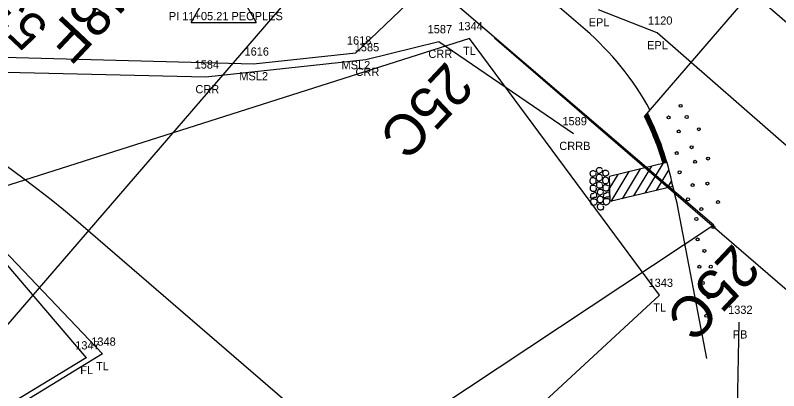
# Model space of a CAD drawing. Extents: x 1812113 to 1819860, y 1177395 to 1181185.
# Drawn here: x 1813697.5 to 1813790.4, y 1178629.6 to 1178675.3 of the extents above; entities that cross this region are included whole.
import ezdxf

# ---------------------------------------------------------------- set-up
doc = ezdxf.new("R2010")
doc.units = 0
for name, color, linetype in [('RD_EX_DR_Pipe', 7, 'Continuous'), ('RD_EX_DR_Pipe_txCode', 7, 'Continuous'), ('RD_EX_Fence_Other', 7, 'Continuous'), ('RD_EX_Fence_Other_txCode', 7, 'Continuous'), ('RD_EX_H2O', 7, 'Continuous'), ('RD_EX_H2O_txCode', 7, 'Continuous'), ('RD_EX_Misc', 7, 'Continuous'), ('RD_EX_Misc_txCode', 7, 'Continuous'), ('RD_EX_Road', 7, 'Continuous'), ('RD_EX_Road_txCode', 7, 'Continuous'), ('RD_EX_RW', 7, 'Continuous'), ('RD_EX_VEG', 7, 'Continuous'), ('RD_EX_VEG_txCode', 7, 'Continuous'), ('RD_HC_Data', 7, 'Continuous'), ('RD_HC_txCode', 7, 'Continuous'), ('RD_PD_ALT1_TrvlWay', 7, 'Continuous'), ('RD_PD_ALT3_LnLine', 7, 'Continuous'), ('RD_PD_Bridge', 7, 'Continuous'), ('RD_PD_PatLn1', 7, 'Continuous'), ('RD_PD_RW', 7, 'Continuous'), ('RD_SMD_Locator', 7, 'Continuous')]:
    doc.layers.add(name, color=color, linetype=linetype)

msp = doc.modelspace()

# ---------------------------------------------------------------- linework, layer by layer
at = {"layer": 'RD_EX_DR_Pipe'}
msp.add_line((1813784.669, 1178591.737), (1813785.572, 1178637.964), dxfattribs=at)
at = {"layer": 'RD_EX_Fence_Other'}
msp.add_lwpolyline([(1813689.162, 1178653.472), (1813706.151, 1178633.635), (1813541.418, 1178533.615)], dxfattribs=at)
at = {"layer": 'RD_EX_H2O'}
msp.add_lwpolyline([(1813494.934, 1178677.139), (1813538.082, 1178685.025), (1813548.669, 1178684.396), (1813554.063, 1178674.831), (1813572.775, 1178667.802), (1813599.795, 1178663.176), (1813623.262, 1178662.124), (1813655.354, 1178662.604), (1813687.646, 1178668.532), (1813720.678, 1178667.781), (1813740.155, 1178669.888), (1813749.02, 1178672.079), (1813765.419, 1178660.888)], dxfattribs=at)
at = {"layer": 'RD_EX_Misc'}
msp.add_lwpolyline([(1813591.145, 1178668.772), (1813628.984, 1178667.844), (1813655.761, 1178668.83), (1813686.954, 1178670.41), (1813726.51, 1178669.36), (1813738.941, 1178670.711), (1813788.676, 1178718.193), (1813806.253, 1178725.658), (1813819.179, 1178726.191), (1813847.084, 1178721.307), (1813860.38, 1178717.648), (1813871.967, 1178724.247), (1813883.921, 1178723.481), (1813902.674, 1178722.415)], dxfattribs=at)
at = {"layer": 'RD_EX_Road'}
for p, q in [((1813775.579, 1178673.127), (1813768.463, 1178675.914)), ((1813800.257, 1178651.571), (1813775.579, 1178673.127))]:
    msp.add_line(p, q, dxfattribs=at)
at = {"layer": 'RD_EX_RW'}
for q in [(1813739.051, 1178686.932), (1813724.979, 1178611.658)]:
    msp.add_line((1813782.499, 1178649.754), q, dxfattribs=at)
at = {"layer": 'RD_EX_VEG'}
msp.add_lwpolyline([(1813569.577, 1178500.764), (1813635.352, 1178535.148), (1813737.799, 1178606.062), (1813775.895, 1178641.246), (1813752.752, 1178672.453), (1813690.463, 1178652.624), (1813708.106, 1178634.089), (1813540.707, 1178531.719)], dxfattribs=at)
at = {"layer": 'RD_HC_Data'}
for p, q in [((1813755.38, 1178705.862), (1813645.021, 1178577.927)), ((1813718.894, 1178674.376), (1813722.866, 1178681.256)), ((1813722.866, 1178681.256), (1813726.835, 1178674.376)), ((1813718.894, 1178674.376), (1813726.835, 1178674.376))]:
    msp.add_line(p, q, dxfattribs=at)
at = {"layer": 'RD_PD_ALT1_TrvlWay'}
for p, q in [((1813774.756, 1178663.814), (1813774.054, 1178663.001)), ((1813776.792, 1178657.372), (1813769.781, 1178655.674)), ((1813774.917, 1178656.918), (1813772.707, 1178653.296)), ((1813776.291, 1178657.251), (1813774.082, 1178653.629)), ((1813770.793, 1178655.919), (1813769.824, 1178654.33)), ((1813772.168, 1178656.252), (1813769.958, 1178652.63)), ((1813773.543, 1178656.585), (1813771.333, 1178652.963)), ((1813777.003, 1178656.498), (1813775.456, 1178653.962)), ((1813769.878, 1178652.611), (1813769.781, 1178655.674)), ((1813777.336, 1178655.123), (1813776.831, 1178654.295)), ((1813777.498, 1178654.456), (1813769.878, 1178652.611)), ((1813781.632, 1178633.542), (1813778.204, 1178651.541))]:
    msp.add_line(p, q, dxfattribs=at)
for centre in [(1813778.439, 1178664.256), (1813776.979, 1178662.847), (1813779.188, 1178662.893), (1813780.666, 1178661.416), (1813778.223, 1178661.141), (1813777.979, 1178658.509), (1813779.786, 1178659.219), (1813781.8, 1178657.843), (1813780.211, 1178657.451), (1813778.326, 1178656.173), (1813781.717, 1178654.805), (1813779.908, 1178654.622), (1813779.344, 1178652.885), (1813782.994, 1178652.546), (1813780.968, 1178651.698), (1813780.362, 1178650.492), (1813782.437, 1178649.505), (1813780.513, 1178648.004), (1813781.349, 1178646.621), (1813780.745, 1178644.684), (1813782.119, 1178644.697), (1813781.142, 1178642.714), (1813781.844, 1178640.982), (1813781.566, 1178638.729)]:
    msp.add_circle(centre, 0.182, dxfattribs=at)
for centre, radius, start, end in [((1813744.086, 1178647.916), 33.935, 16.13386, 26.98789), ((1813744.086, 1178647.916), 33.99, 16.12977, 27.02575), ((1813744.086, 1178647.916), 34.045, 11.0753, 27.06348), ((1813744.086, 1178647.916), 33.55, 16.1628, 26.71909), ((1813744.086, 1178647.916), 33.605, 16.15862, 26.7579), ((1813744.086, 1178647.916), 33.66, 16.15446, 26.79657), ((1813744.086, 1178647.916), 33.715, 16.15031, 26.83511), ((1813744.086, 1178647.916), 33.77, 16.14618, 26.87351), ((1813744.086, 1178647.916), 33.825, 16.14206, 26.91177), ((1813744.086, 1178647.916), 33.88, 16.13795, 26.9499), ((1813744.322, 1178644.902), 34.526, 11.08496, 17.1518)]:
    msp.add_arc(centre, radius, start, end, dxfattribs=at)
for points in [[(1813768.14, 1178656.085), (1813768.127, 1178655.891), (1813768.019, 1178655.757), (1813767.866, 1178655.684), (1813767.674, 1178655.647), (1813767.54, 1178655.754), (1813767.478, 1178655.933), (1813767.46, 1178656.113), (1813767.53, 1178656.264), (1813767.664, 1178656.368), (1813767.844, 1178656.38), (1813768.014, 1178656.317), (1813768.136, 1178656.203)], [(1813768.913, 1178655.623), (1813768.919, 1178655.436), (1813768.856, 1178655.26), (1813768.71, 1178655.162), (1813768.531, 1178655.094), (1813768.362, 1178655.145), (1813768.276, 1178655.298), (1813768.208, 1178655.476), (1813768.215, 1178655.657), (1813768.297, 1178655.809), (1813768.43, 1178655.937), (1813768.617, 1178655.937), (1813768.788, 1178655.849), (1813768.904, 1178655.697)], [(1813768.911, 1178656.475), (1813768.898, 1178656.282), (1813768.791, 1178656.148), (1813768.637, 1178656.074), (1813768.445, 1178656.037), (1813768.311, 1178656.145), (1813768.25, 1178656.324), (1813768.232, 1178656.503), (1813768.301, 1178656.655), (1813768.435, 1178656.759), (1813768.615, 1178656.771), (1813768.785, 1178656.708), (1813768.907, 1178656.593)], [(1813769.675, 1178656.133), (1813769.662, 1178655.94), (1813769.555, 1178655.806), (1813769.401, 1178655.732), (1813769.209, 1178655.695), (1813769.075, 1178655.803), (1813769.014, 1178655.982), (1813768.995, 1178656.161), (1813769.065, 1178656.313), (1813769.199, 1178656.417), (1813769.379, 1178656.429), (1813769.549, 1178656.366), (1813769.671, 1178656.251)], [(1813768.142, 1178655.232), (1813768.148, 1178655.046), (1813768.085, 1178654.869), (1813767.939, 1178654.771), (1813767.76, 1178654.704), (1813767.59, 1178654.754), (1813767.505, 1178654.907), (1813767.437, 1178655.085), (1813767.443, 1178655.266), (1813767.526, 1178655.418), (1813767.659, 1178655.547), (1813767.846, 1178655.546), (1813768.016, 1178655.458), (1813768.133, 1178655.307)], [(1813768.9, 1178654.725), (1813768.971, 1178654.496), (1813768.83, 1178654.282), (1813768.643, 1178654.234), (1813768.474, 1178654.249), (1813768.302, 1178654.37), (1813768.254, 1178654.557), (1813768.249, 1178654.725), (1813768.286, 1178654.894), (1813768.429, 1178655.004), (1813768.597, 1178655.009), (1813768.767, 1178654.951), (1813768.917, 1178654.851)], [(1813769.677, 1178655.281), (1813769.683, 1178655.094), (1813769.62, 1178654.918), (1813769.474, 1178654.82), (1813769.295, 1178654.752), (1813769.126, 1178654.803), (1813769.04, 1178654.956), (1813768.972, 1178655.134), (1813768.979, 1178655.315), (1813769.061, 1178655.467), (1813769.194, 1178655.595), (1813769.381, 1178655.595), (1813769.552, 1178655.507), (1813769.668, 1178655.355)], [(1813768.129, 1178654.334), (1813768.2, 1178654.105), (1813768.059, 1178653.891), (1813767.872, 1178653.843), (1813767.703, 1178653.859), (1813767.531, 1178653.979), (1813767.483, 1178654.167), (1813767.478, 1178654.335), (1813767.515, 1178654.504), (1813767.658, 1178654.613), (1813767.826, 1178654.619), (1813767.996, 1178654.561), (1813768.146, 1178654.461)], [(1813769.015, 1178653.824), (1813769.003, 1178653.63), (1813768.895, 1178653.496), (1813768.741, 1178653.423), (1813768.55, 1178653.386), (1813768.415, 1178653.493), (1813768.354, 1178653.672), (1813768.336, 1178653.852), (1813768.406, 1178654.003), (1813768.539, 1178654.107), (1813768.719, 1178654.119), (1813768.89, 1178654.056), (1813769.011, 1178653.942)], [(1813769.664, 1178654.383), (1813769.735, 1178654.154), (1813769.594, 1178653.94), (1813769.407, 1178653.892), (1813769.238, 1178653.907), (1813769.066, 1178654.028), (1813769.018, 1178654.215), (1813769.013, 1178654.383), (1813769.05, 1178654.552), (1813769.193, 1178654.662), (1813769.361, 1178654.667), (1813769.531, 1178654.609), (1813769.681, 1178654.509)], [(1813768.172, 1178653.643), (1813768.198, 1178653.475), (1813768.225, 1178653.308), (1813768.167, 1178653.138), (1813768, 1178653.112), (1813767.833, 1178653.086), (1813767.667, 1178653.018), (1813767.497, 1178653.054), (1813767.512, 1178653.244), (1813767.548, 1178653.434), (1813767.649, 1178653.584), (1813767.817, 1178653.589), (1813767.939, 1178653.719), (1813768.128, 1178653.725)], [(1813769.017, 1178652.971), (1813769.023, 1178652.785), (1813768.96, 1178652.608), (1813768.814, 1178652.51), (1813768.635, 1178652.442), (1813768.466, 1178652.493), (1813768.38, 1178652.646), (1813768.312, 1178652.824), (1813768.319, 1178653.005), (1813768.401, 1178653.157), (1813768.534, 1178653.286), (1813768.721, 1178653.285), (1813768.892, 1178653.197), (1813769.009, 1178653.045)], [(1813769.738, 1178653.692), (1813769.764, 1178653.525), (1813769.79, 1178653.358), (1813769.733, 1178653.188), (1813769.565, 1178653.162), (1813769.398, 1178653.135), (1813769.232, 1178653.067), (1813769.063, 1178653.104), (1813769.078, 1178653.293), (1813769.114, 1178653.483), (1813769.214, 1178653.634), (1813769.382, 1178653.639), (1813769.504, 1178653.769), (1813769.693, 1178653.775)], [(1813768.29, 1178652.575), (1813768.212, 1178652.384), (1813768.091, 1178652.233), (1813767.925, 1178652.165), (1813767.757, 1178652.139), (1813767.563, 1178652.321), (1813767.536, 1178652.489), (1813767.531, 1178652.656), (1813767.568, 1178652.826), (1813767.711, 1178652.935), (1813767.879, 1178652.94), (1813768.048, 1178652.925), (1813768.218, 1178652.846), (1813768.266, 1178652.68)], [(1813769.005, 1178652.073), (1813769.075, 1178651.844), (1813768.935, 1178651.63), (1813768.747, 1178651.582), (1813768.578, 1178651.598), (1813768.407, 1178651.718), (1813768.359, 1178651.906), (1813768.353, 1178652.073), (1813768.39, 1178652.243), (1813768.534, 1178652.352), (1813768.702, 1178652.358), (1813768.871, 1178652.3), (1813769.022, 1178652.2)], [(1813769.825, 1178652.624), (1813769.747, 1178652.432), (1813769.626, 1178652.282), (1813769.46, 1178652.213), (1813769.293, 1178652.187), (1813769.098, 1178652.37), (1813769.071, 1178652.537), (1813769.066, 1178652.705), (1813769.103, 1178652.874), (1813769.246, 1178652.984), (1813769.414, 1178652.989), (1813769.583, 1178652.973), (1813769.753, 1178652.895), (1813769.801, 1178652.728)]]:
    msp.add_spline(points, degree=3, dxfattribs=at)
at = {"layer": 'RD_PD_ALT3_LnLine'}
for p, q in [((1813708.91, 1178675.057), (1813703.908, 1178678.505)), ((1813793.673, 1178639.815), (1813755.812, 1178672.473))]:
    msp.add_line(p, q, dxfattribs=at)
at = {"layer": 'RD_PD_Bridge'}
for p, q in [((1813798.39, 1178691.213), (1813774.756, 1178663.814)), ((1813766.835, 1178673.53), (1813761.038, 1178678.531))]:
    msp.add_line(p, q, dxfattribs=at)
msp.add_arc((1813743.974, 1178647.028), 35, 28.56748, 49.21843, dxfattribs=at)
at = {"layer": 'RD_PD_PatLn1'}
msp.add_line((1813775.635, 1178688.143), (1813886.049, 1178591.554), dxfattribs=at)
at = {"layer": 'RD_PD_RW'}
msp.add_line((1813739, 1178620.944), (1813706.392, 1178649.072), dxfattribs=at)
msp.add_arc((1813611.441, 1178538.999), 145.368, 49.21843, 73.8831, dxfattribs=at)
at = {"layer": 'RD_SMD_Locator'}
for centre in [(1813775.579, 1178673.127), (1813749.02, 1178672.079), (1813752.752, 1178672.453), (1813738.941, 1178670.711), (1813740.155, 1178669.888), (1813726.51, 1178669.36), (1813720.678, 1178667.781), (1813765.419, 1178660.888), (1813775.895, 1178641.246), (1813785.572, 1178637.964), (1813706.151, 1178633.635), (1813708.106, 1178634.089)]:
    msp.add_circle(centre, 0.001, dxfattribs=at)

# ---------------------------------------------------------------- texts
at = {"layer": 'RD_EX_DR_Pipe_txCode'}
for s, p in [('1332', (1813784.225, 1178638.964)), ('PB', (1813784.792, 1178635.964))]:
    msp.add_text(s, height=1, dxfattribs=at).set_placement(p)
at = {"layer": 'RD_EX_Fence_Other_txCode'}
for s, p in [('1347', (1813704.805, 1178634.635)), ('FL', (1813705.419, 1178631.635))]:
    msp.add_text(s, height=1, dxfattribs=at).set_placement(p)
at = {"layer": 'RD_EX_H2O_txCode'}
for s, p in [('1587', (1813747.674, 1178673.079)), ('1585', (1813738.809, 1178670.888)), ('CRR', (1813747.768, 1178670.079)), ('1584', (1813719.332, 1178668.781)), ('CRR', (1813738.903, 1178667.888)), ('CRR', (1813719.426, 1178665.781)), ('1589', (1813764.073, 1178661.888)), ('CRRB', (1813763.695, 1178658.888))]:
    msp.add_text(s, height=1, dxfattribs=at).set_placement(p)
at = {"layer": 'RD_EX_Misc_txCode'}
for s, p in [('1618', (1813737.854, 1178671.711)), ('1616', (1813725.4, 1178670.36)), ('MSL2', (1813737.2, 1178668.711)), ('MSL2', (1813724.77, 1178667.36))]:
    msp.add_text(s, height=1, dxfattribs=at).set_placement(p)
at = {"layer": 'RD_EX_Road_txCode'}
for s, p in [('EPL', (1813767.258, 1178673.914)), ('1120', (1813774.476, 1178674.127)), ('EPL', (1813774.374, 1178671.127))]:
    msp.add_text(s, height=1, dxfattribs=at).set_placement(p)
at = {"layer": 'RD_EX_VEG_txCode'}
for s, p in [('1344', (1813751.406, 1178673.453)), ('TL', (1813751.981, 1178670.453)), ('1343', (1813774.549, 1178642.246)), ('TL', (1813775.123, 1178639.246)), ('1348', (1813706.759, 1178635.089)), ('TL', (1813707.334, 1178632.089))]:
    msp.add_text(s, height=1, dxfattribs=at).set_placement(p)
at = {"layer": 'RD_HC_txCode'}
msp.add_text('PI 11+05.21 PEOPLES', height=1, dxfattribs=at).set_placement((1813716.196, 1178674.669))
at = {"layer": 'RD_PD_ALT3_LnLine'}
for s, height, rotation, p in [('48F', 5, 226.72337, (1813708.703, 1178680.977)), ('53', 4.5, 136.72337, (1813701.756, 1178673.925)), ('25C', 5, 226.72337, (1813749.976, 1178669.804)), ('25C', 5, 226.72337, (1813784.862, 1178647.676))]:
    msp.add_text(s, height=height, rotation=rotation, dxfattribs=at).set_placement(p)

doc.saveas('drawing.dxf')
